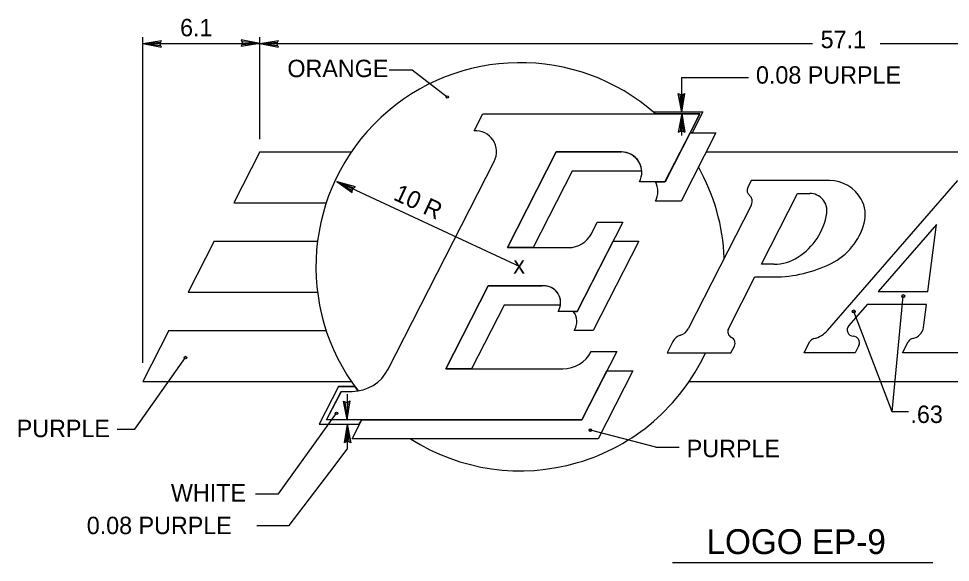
# Model space of a CAD drawing. Extents: x 10268197 to 10268826, y 2141503 to 2142677.
# Drawn here: x 10268493.16 to 10268525.45, y 2142387.11 to 2142405.97 of the extents above; entities that cross this region are included whole.
import ezdxf

# ---------------------------------------------------------------- set-up
doc = ezdxf.new("R2010")
doc.units = 0
for name, color, linetype in [('1', 7, 'Continuous'), ('Default', 7, 'Continuous'), ('TextDetails', 7, 'Continuous')]:
    doc.layers.add(name, color=color, linetype=linetype)

msp = doc.modelspace()

# ---------------------------------------------------------------- linework, layer by layer
at = {"layer": '1'}
for p, q in [((10268497.462, 2142394.031), (10268497.462, 2142405.328)), ((10268501.516, 2142401.788), (10268501.516, 2142405.328)), ((10268497.462, 2142405.107), (10268520.664, 2142405.107)), ((10268523.019, 2142405.107), (10268542.219, 2142405.107)), ((10268505.993, 2142404.196), (10268506.794, 2142404.196)), ((10268506.794, 2142404.196), (10268508.014, 2142403.253)), ((10268516.142, 2142403.93), (10268518.449, 2142403.93)), ((10268516.142, 2142402.759), (10268516.142, 2142403.93)), ((10268516.142, 2142401.916), (10268516.142, 2142402.679)), ((10268510.541, 2142397.364), (10268504.188, 2142400.326)), ((10268523.427, 2142392.326), (10268523.814, 2142396.344)), ((10268523.427, 2142392.326), (10268522.099, 2142395.815)), ((10268497.184, 2142391.735), (10268498.942, 2142394.214)), ((10268504.54, 2142392.941), (10268504.54, 2142392.062)), ((10268502.166, 2142389.491), (10268504.173, 2142392.28)), ((10268523.999, 2142392.326), (10268523.427, 2142392.326)), ((10268496.57, 2142391.735), (10268497.184, 2142391.735)), ((10268504.54, 2142391.905), (10268504.54, 2142391.032)), ((10268515.243, 2142391.1), (10268512.971, 2142391.694)), ((10268503.94, 2142390.24), (10268504.54, 2142391.032)), ((10268515.243, 2142391.1), (10268516.044, 2142391.1)), ((10268502.535, 2142388.386), (10268503.94, 2142390.24)), ((10268501.364, 2142389.491), (10268502.166, 2142389.491)), ((10268501.412, 2142388.386), (10268502.535, 2142388.386))]:
    msp.add_line(p, q, dxfattribs=at)
for centre, radius in [((10268508.014, 2142403.253), 0.0442), ((10268523.814, 2142396.344), 0.0518), ((10268522.099, 2142395.815), 0.0518), ((10268498.942, 2142394.213), 0.0442), ((10268504.173, 2142392.279), 0.0442), ((10268512.971, 2142391.693), 0.0442)]:
    msp.add_circle(centre, radius, dxfattribs=at)
at = {"layer": 'Default'}
for p, q in [((10268497.462, 2142405.107), (10268498.109, 2142405.209)), ((10268498.057, 2142405.096), (10268498.109, 2142405.209)), ((10268501.516, 2142405.107), (10268500.872, 2142405.231)), ((10268500.872, 2142405.231), (10268500.92, 2142405.117)), ((10268501.516, 2142405.107), (10268502.162, 2142405.209)), ((10268502.111, 2142405.096), (10268502.162, 2142405.209)), ((10268497.462, 2142405.107), (10268498.081, 2142405.15)), ((10268497.462, 2142405.107), (10268498.105, 2142404.982)), ((10268497.462, 2142405.107), (10268498.08, 2142405.042)), ((10268498.105, 2142404.982), (10268498.057, 2142405.096)), ((10268500.92, 2142405.117), (10268500.869, 2142405.004)), ((10268501.516, 2142405.107), (10268500.869, 2142405.004)), ((10268501.516, 2142405.107), (10268500.896, 2142405.063)), ((10268501.516, 2142405.107), (10268500.897, 2142405.171)), ((10268501.516, 2142405.107), (10268502.135, 2142405.15)), ((10268501.516, 2142405.107), (10268502.158, 2142404.982)), ((10268501.516, 2142405.107), (10268502.133, 2142405.042)), ((10268502.158, 2142404.982), (10268502.111, 2142405.096)), ((10268516.143, 2142402.727), (10268516.019, 2142403.37)), ((10268516.019, 2142403.37), (10268516.133, 2142403.323)), ((10268516.143, 2142402.727), (10268516.079, 2142403.346)), ((10268516.133, 2142403.323), (10268516.246, 2142403.374)), ((10268516.143, 2142402.727), (10268516.246, 2142403.374)), ((10268516.143, 2142402.727), (10268516.187, 2142403.347)), ((10268508.94, 2142402.08), (10268509.242, 2142402.673)), ((10268509.242, 2142402.673), (10268516.763, 2142402.673)), ((10268515.146, 2142402.739), (10268516.871, 2142402.739)), ((10268516.763, 2142402.673), (10268515.558, 2142400.308)), ((10268516.143, 2142402.675), (10268516.019, 2142402.032)), ((10268516.143, 2142402.675), (10268516.079, 2142402.056)), ((10268516.143, 2142402.675), (10268516.246, 2142402.028)), ((10268516.143, 2142402.675), (10268516.187, 2142402.055)), ((10268516.871, 2142402.739), (10268516.499, 2142402.01)), ((10268515.557, 2142400.305), (10268516.426, 2142402.01)), ((10268515.557, 2142400.305), (10268516.426, 2142402.01)), ((10268516.019, 2142402.032), (10268516.133, 2142402.079)), ((10268517.319, 2142402.01), (10268516.114, 2142399.644)), ((10268517.319, 2142402.01), (10268516.114, 2142399.644)), ((10268516.133, 2142402.079), (10268516.246, 2142402.028)), ((10268516.426, 2142402.01), (10268517.319, 2142402.01)), ((10268516.426, 2142402.01), (10268517.319, 2142402.01)), ((10268501.516, 2142401.346), (10268500.615, 2142399.576)), ((10268501.516, 2142401.346), (10268504.688, 2142401.346)), ((10268511.791, 2142401.346), (10268510.1, 2142398.028)), ((10268510.1, 2142398.028), (10268511.791, 2142401.346)), ((10268510.1, 2142398.028), (10268511.791, 2142401.346)), ((10268514.046, 2142401.346), (10268511.791, 2142401.346)), ((10268511.791, 2142401.346), (10268514.046, 2142401.346)), ((10268511.791, 2142401.346), (10268514.046, 2142401.346)), ((10268516.98, 2142401.346), (10268542.219, 2142401.346)), ((10268505.967, 2142393.813), (10268509.639, 2142401.02)), ((10268512.346, 2142400.682), (10268510.994, 2142398.028)), ((10268512.346, 2142400.682), (10268510.994, 2142398.028)), ((10268514.753, 2142400.682), (10268512.346, 2142400.682)), ((10268514.753, 2142400.682), (10268512.346, 2142400.682)), ((10268518.549, 2142400.35), (10268518.428, 2142400.114)), ((10268521.258, 2142400.35), (10268518.549, 2142400.35)), ((10268521.19, 2142395.154), (10268525.708, 2142400.35)), ((10268504.188, 2142400.326), (10268504.817, 2142400.146)), ((10268504.188, 2142400.326), (10268504.718, 2142399.942)), ((10268504.188, 2142400.326), (10268504.721, 2142400.007)), ((10268504.188, 2142400.326), (10268504.768, 2142400.104)), ((10268504.718, 2142399.942), (10268504.723, 2142400.066)), ((10268504.723, 2142400.066), (10268504.817, 2142400.146)), ((10268515.558, 2142400.308), (10268514.673, 2142400.308)), ((10268515.228, 2142400.305), (10268515.557, 2142400.305)), ((10268515.228, 2142400.305), (10268515.557, 2142400.305)), ((10268518.896, 2142397.453), (10268520.148, 2142399.908)), ((10268520.148, 2142399.908), (10268520.574, 2142399.908)), ((10268500.615, 2142399.576), (10268503.817, 2142399.576)), ((10268516.114, 2142399.644), (10268515.229, 2142399.644)), ((10268516.114, 2142399.644), (10268515.229, 2142399.644)), ((10268518.556, 2142399.514), (10268516.366, 2142395.215)), ((10268514.095, 2142398.913), (10268512.517, 2142395.816)), ((10268513.005, 2142398.511), (10268513.21, 2142398.913)), ((10268513.21, 2142398.913), (10268514.095, 2142398.913)), ((10268524.967, 2142398.824), (10268522.948, 2142396.501)), ((10268524.665, 2142396.501), (10268524.967, 2142398.824)), ((10268499.939, 2142398.249), (10268499.039, 2142396.479)), ((10268499.939, 2142398.249), (10268503.517, 2142398.249)), ((10268512.517, 2142395.816), (10268513.757, 2142398.249)), ((10268512.517, 2142395.816), (10268513.757, 2142398.249)), ((10268514.651, 2142398.249), (10268513.072, 2142395.152)), ((10268514.651, 2142398.249), (10268513.072, 2142395.152)), ((10268513.757, 2142398.249), (10268514.651, 2142398.249)), ((10268513.757, 2142398.249), (10268514.651, 2142398.249)), ((10268510.1, 2142398.028), (10268512.217, 2142398.028)), ((10268510.994, 2142398.028), (10268510.1, 2142398.028)), ((10268510.994, 2142398.028), (10268510.1, 2142398.028)), ((10268519.334, 2142397.453), (10268518.896, 2142397.453)), ((10268517.755, 2142395.215), (10268518.67, 2142397.01)), ((10268518.67, 2142397.01), (10268519.334, 2142397.01)), ((10268499.039, 2142396.479), (10268503.517, 2142396.479)), ((10268509.424, 2142396.701), (10268507.959, 2142393.825)), ((10268507.959, 2142393.825), (10268509.424, 2142396.701)), ((10268507.959, 2142393.825), (10268509.424, 2142396.701)), ((10268511.366, 2142396.701), (10268509.424, 2142396.701)), ((10268509.424, 2142396.701), (10268511.283, 2142396.694)), ((10268509.424, 2142396.701), (10268511.283, 2142396.694)), ((10268522.948, 2142396.501), (10268524.665, 2142396.501)), ((10268509.979, 2142396.035), (10268508.853, 2142393.825)), ((10268509.979, 2142396.035), (10268508.853, 2142393.825)), ((10268511.933, 2142396.029), (10268509.979, 2142396.035)), ((10268511.933, 2142396.029), (10268509.979, 2142396.035)), ((10268522.564, 2142396.058), (10268521.923, 2142395.322)), ((10268524.62, 2142396.058), (10268522.564, 2142396.058)), ((10268524.515, 2142395.259), (10268524.62, 2142396.058)), ((10268512.517, 2142395.816), (10268511.851, 2142395.816)), ((10268512.378, 2142395.816), (10268512.517, 2142395.816)), ((10268512.378, 2142395.816), (10268512.517, 2142395.816)), ((10268498.363, 2142395.152), (10268497.462, 2142393.382)), ((10268498.363, 2142395.152), (10268503.817, 2142395.152)), ((10268513.072, 2142395.152), (10268512.409, 2142395.152)), ((10268513.072, 2142395.152), (10268512.409, 2142395.152)), ((10268515.828, 2142394.768), (10268515.629, 2142394.377)), ((10268517.841, 2142394.377), (10268517.961, 2142394.614)), ((10268520.376, 2142394.377), (10268520.569, 2142394.756)), ((10268522.276, 2142394.633), (10268522.146, 2142394.377)), ((10268523.791, 2142394.377), (10268523.986, 2142394.762)), ((10268513.886, 2142394.42), (10268512.681, 2142392.055)), ((10268513.001, 2142394.42), (10268513.886, 2142394.42)), ((10268515.629, 2142394.377), (10268517.841, 2142394.377)), ((10268522.146, 2142394.377), (10268520.376, 2142394.377)), ((10268526.003, 2142394.377), (10268523.791, 2142394.377)), ((10268507.959, 2142393.825), (10268512.019, 2142393.825)), ((10268508.853, 2142393.825), (10268507.959, 2142393.825)), ((10268508.853, 2142393.825), (10268507.959, 2142393.825)), ((10268512.681, 2142392.055), (10268513.547, 2142393.757)), ((10268512.681, 2142392.055), (10268513.547, 2142393.757)), ((10268514.442, 2142393.757), (10268513.236, 2142391.392)), ((10268514.442, 2142393.757), (10268513.236, 2142391.392)), ((10268513.547, 2142393.757), (10268514.442, 2142393.757)), ((10268513.547, 2142393.757), (10268514.442, 2142393.757)), ((10268497.462, 2142393.382), (10268504.688, 2142393.382)), ((10268516.394, 2142393.382), (10268538.161, 2142393.382)), ((10268504.241, 2142393.213), (10268503.576, 2142391.905)), ((10268503.832, 2142392.055), (10268504.334, 2142393.04)), ((10268504.241, 2142393.213), (10268504.806, 2142393.213)), ((10268504.334, 2142393.04), (10268504.706, 2142393.04)), ((10268504.54, 2142392.062), (10268504.415, 2142392.704)), ((10268504.415, 2142392.704), (10268504.53, 2142392.657)), ((10268504.54, 2142392.062), (10268504.475, 2142392.68)), ((10268504.53, 2142392.657), (10268504.643, 2142392.708)), ((10268504.54, 2142392.062), (10268504.643, 2142392.708)), ((10268504.54, 2142392.062), (10268504.583, 2142392.681)), ((10268512.681, 2142392.055), (10268503.832, 2142392.055)), ((10268504.717, 2142391.392), (10268505.055, 2142392.055)), ((10268504.717, 2142391.392), (10268505.055, 2142392.055)), ((10268505.055, 2142392.055), (10268512.681, 2142392.055)), ((10268505.055, 2142392.055), (10268512.681, 2142392.055)), ((10268503.576, 2142391.905), (10268504.964, 2142391.905)), ((10268504.54, 2142391.905), (10268504.437, 2142391.258)), ((10268504.54, 2142391.905), (10268504.497, 2142391.285)), ((10268504.54, 2142391.905), (10268504.665, 2142391.261)), ((10268504.54, 2142391.905), (10268504.605, 2142391.286)), ((10268504.55, 2142391.309), (10268504.437, 2142391.258)), ((10268504.665, 2142391.261), (10268504.55, 2142391.309)), ((10268513.236, 2142391.392), (10268504.717, 2142391.392)), ((10268513.236, 2142391.392), (10268504.717, 2142391.392))]:
    msp.add_line(p, q, dxfattribs=at)
for points in [[(10268515.146, 2142402.739), (10268516.871, 2142402.739), (10268516.499, 2142402.01), (10268516.426, 2142402.01), (10268516.763, 2142402.673), (10268515.223, 2142402.672)], [(10268504.806, 2142393.213), (10268504.241, 2142393.213), (10268503.576, 2142391.905), (10268504.964, 2142391.905), (10268505.055, 2142392.055), (10268503.832, 2142392.055), (10268504.348, 2142393.04), (10268504.711, 2142393.04), (10268504.923, 2142393.057)]]:
    msp.add_lwpolyline(points, close=True, dxfattribs=at)
for centre, radius, start, end in [((10268510.541, 2142397.363), 7.079, 48.5904, 217.4727), ((10268508.988, 2142401.351), 0.73, 332.9998, 93.8045), ((10268514.046, 2142400.637), 0.708, 332.2089, 90), ((10268514.046, 2142400.637), 0.708, 3.5833, 90), ((10268514.046, 2142400.637), 0.708, 3.5833, 90), ((10268510.541, 2142397.363), 7.079, 2.4236, 29.2771), ((10268521.258, 2142399.089), 1.261, 29.4315, 90), ((10268514.602, 2142399.974), 0.708, 332.2089, 27.9127), ((10268514.602, 2142399.974), 0.708, 332.2089, 27.9127), ((10268518.625, 2142400.013), 0.221, 152.9784, 231.1602), ((10268518.32, 2142399.634), 0.265, 333.0027, 51.1602), ((10268520.574, 2142399.31), 0.597, 351.076, 90), ((10268521.393, 2142399.165), 1.106, 344.7074, 29.4315), ((10268518.978, 2142399.561), 2.212, 302.4206, 351.076), ((10268520.326, 2142399.456), 2.212, 296.6431, 344.7074), ((10268512.217, 2142398.912), 0.885, 270, 332.9883), ((10268519.334, 2142399), 1.548, 270, 302.4206), ((10268519.334, 2142401.434), 4.424, 270, 296.6431), ((10268511.366, 2142396.125), 0.575, 350.3502, 98.3344), ((10268511.366, 2142396.125), 0.575, 350.3502, 98.3344), ((10268511.366, 2142396.125), 0.575, 327.421, 90), ((10268511.925, 2142395.461), 0.575, 327.421, 37.9799), ((10268511.925, 2142395.461), 0.575, 327.421, 37.9799), ((10268515.972, 2142395.415), 0.442, 286.4317, 332.9959), ((10268517.953, 2142395.114), 0.221, 152.9884, 244.7832), ((10268522.09, 2142395.176), 0.221, 138.9824, 268.6869), ((10268524.077, 2142395.316), 0.442, 279.2397, 352.5632), ((10268516.222, 2142394.566), 0.442, 106.4317, 152.9742), ((10268517.764, 2142394.714), 0.221, 333.0239, 64.7832), ((10268520.766, 2142394.655), 0.221, 102.7162, 153.0239), ((10268520.523, 2142395.734), 0.885, 282.7162, 318.9966), ((10268522.079, 2142394.733), 0.221, 332.9784, 88.6869), ((10268524.183, 2142394.661), 0.221, 99.2397, 153.0239), ((10268510.541, 2142397.363), 7.079, 237.5383, 335.047), ((10268512.019, 2142394.93), 1.106, 270, 332.5096), ((10268504.706, 2142394.456), 1.416, 270, 332.9991)]:
    msp.add_arc(centre, radius, start, end, dxfattribs=at)
at = {"layer": 'TextDetails'}
msp.add_line((10268515.816, 2142387.109), (10268524.842, 2142387.109), dxfattribs=at)

# ---------------------------------------------------------------- texts
at = {"layer": '1'}
for s, height, p in [('6.1', 0.6037, (10268498.753, 2142405.358)), ('57.1', 0.6037, (10268520.951, 2142404.945)), ('ORANGE', 0.6037, (10268502.472, 2142403.941)), ('0.08 PURPLE', 0.60368, (10268518.71, 2142403.715)), ('x', 0.604, (10268510.301, 2142397.128)), ('.63', 0.6037, (10268524.064, 2142391.944)), ('PURPLE', 0.6037, (10268493.092, 2142391.453)), ('PURPLE', 0.6037, (10268516.311, 2142390.758)), ('WHITE', 0.6037, (10268498.436, 2142389.22)), ('0.08 PURPLE', 0.60368, (10268495.519, 2142388.089))]:
    msp.add_text(s, height=height, dxfattribs=at).set_placement(p)
msp.add_text('10 R', height=0.6037, rotation=334.9991, dxfattribs=at).set_placement((10268506.109, 2142399.705))
at = {"layer": 'TextDetails'}
msp.add_text('LOGO EP-9', height=0.8624, dxfattribs=at).set_placement((10268516.995, 2142387.397))

doc.saveas('drawing.dxf')
